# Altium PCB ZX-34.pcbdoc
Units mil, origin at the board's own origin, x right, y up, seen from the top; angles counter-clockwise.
Board outline 1066.93 x 1196.85 mil, 2 copper layers (Top Layer, Bottom Layer); 1 components, 0 nets, 21 pads, 0 vias.
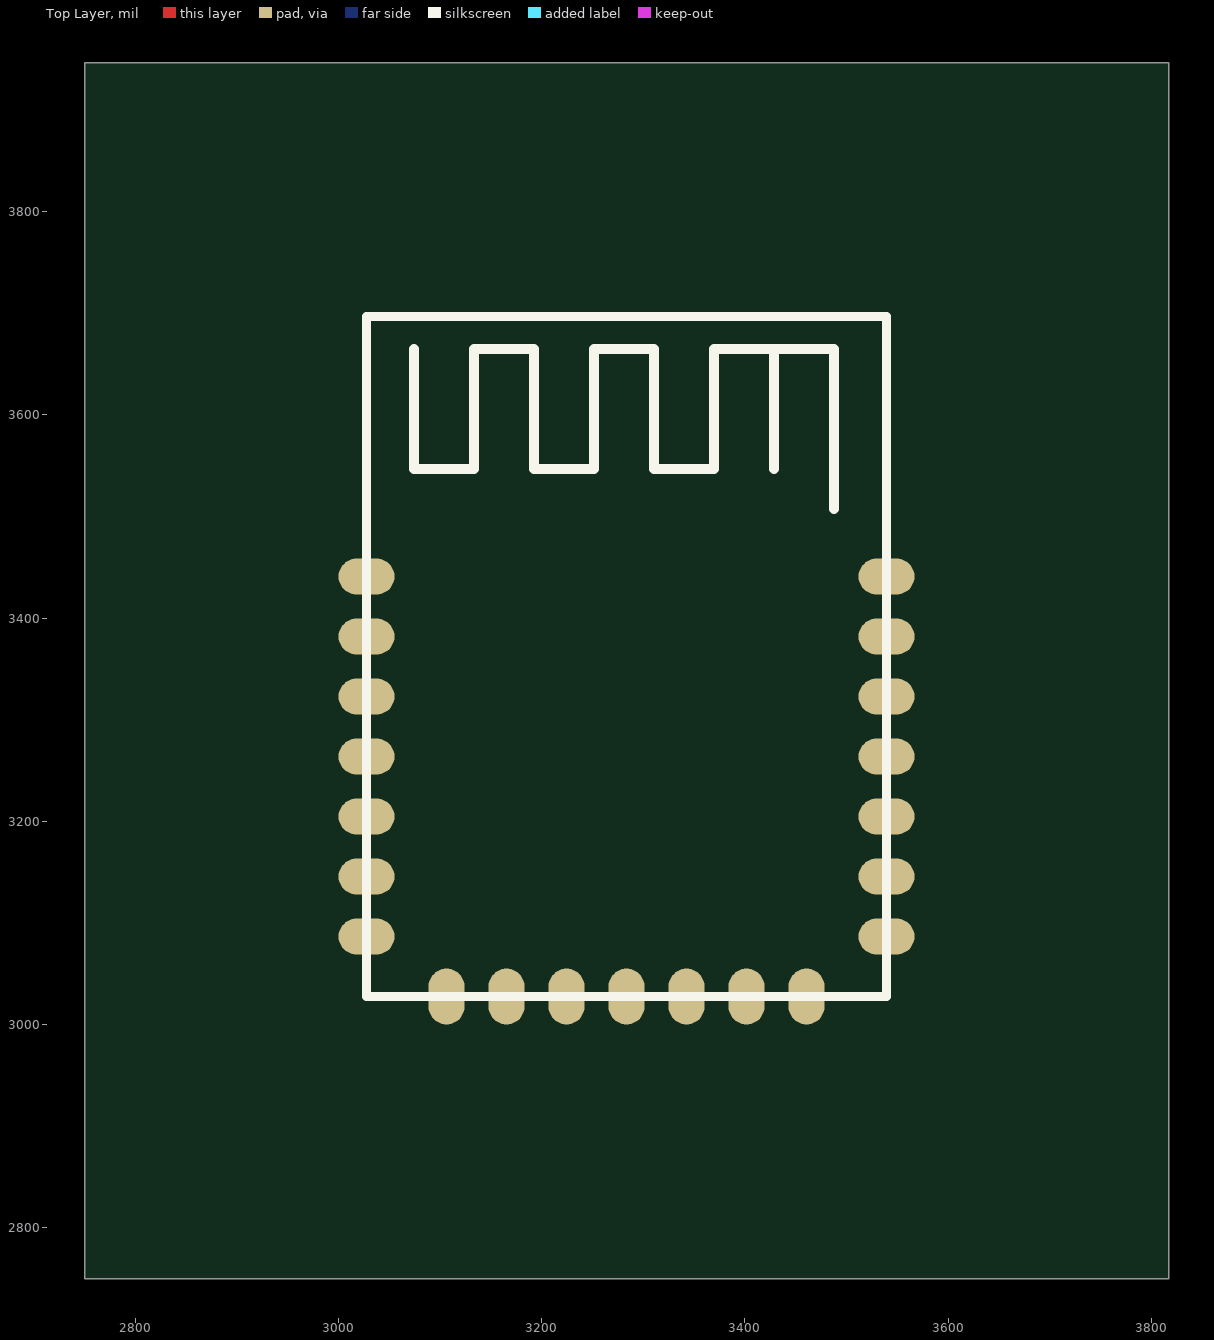
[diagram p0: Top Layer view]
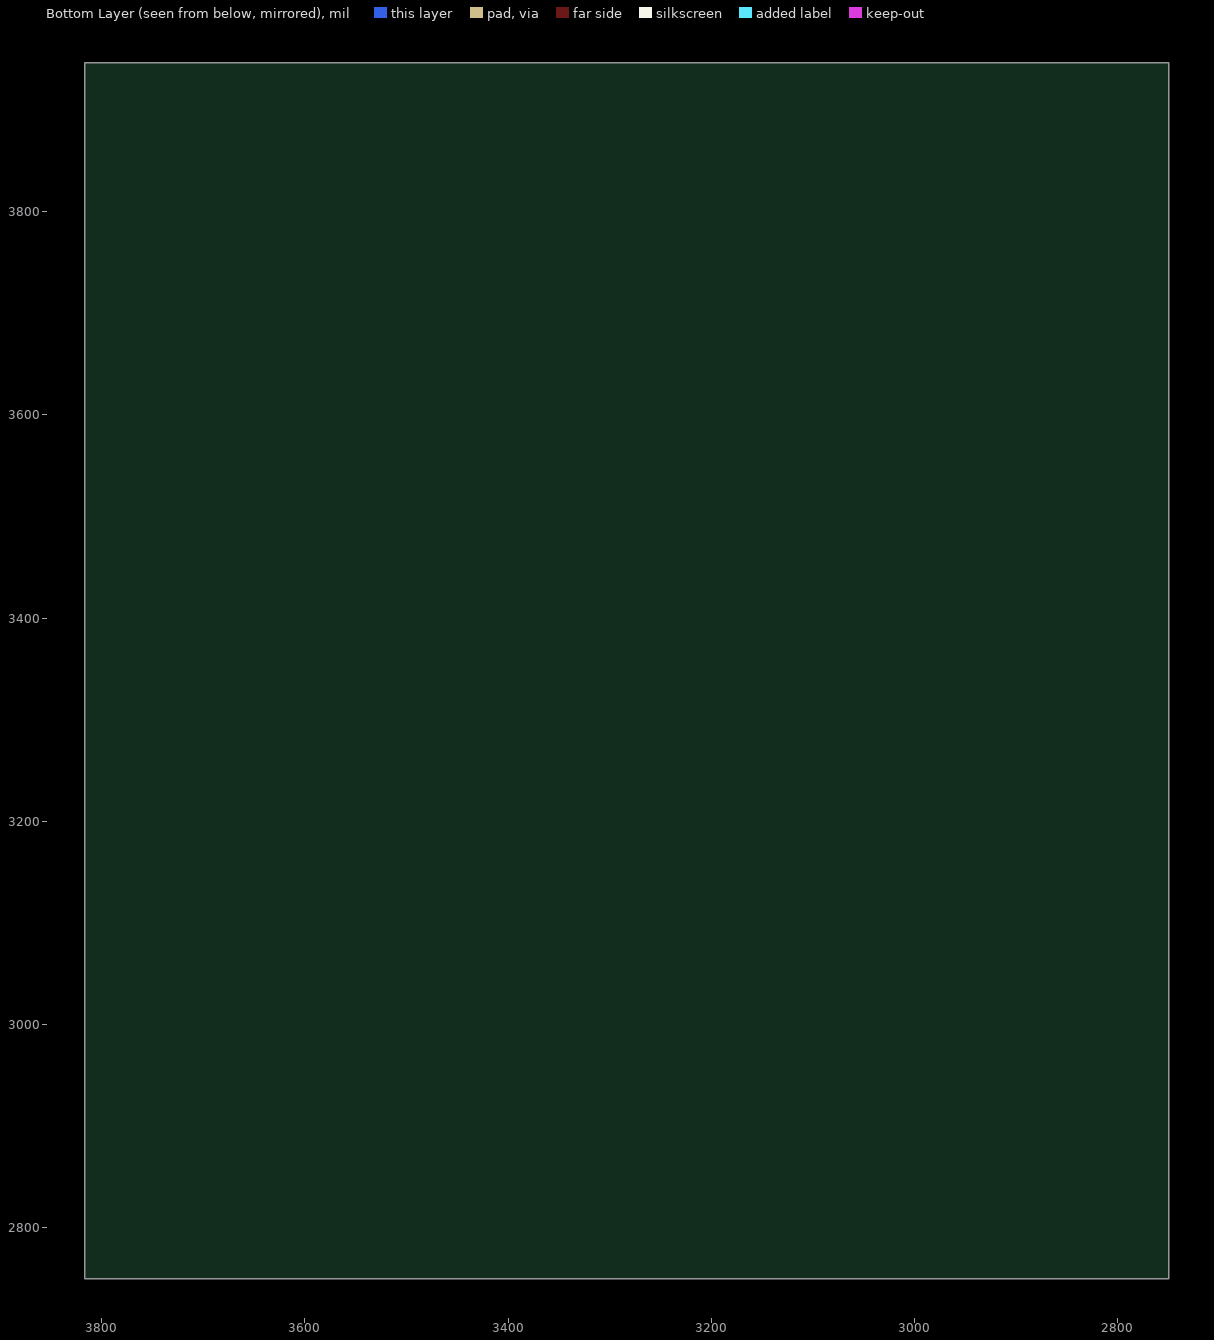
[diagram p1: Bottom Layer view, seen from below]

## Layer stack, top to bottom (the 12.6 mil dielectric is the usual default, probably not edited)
Top Solder Mask Layer: solder mask 0.4, Solder Resist, Dk 3.5
Top Layer: signal copper 1.4
Dielectric1: dielectric 12.6, FR-4, Dk 4.8
Bottom Layer: signal copper 1.4
Bottom Solder Mask Layer: solder mask 0.4, Solder Resist, Dk 3.5

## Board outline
3816.93,2750 2750,2750 2750,3946.85 3816.93,3946.85

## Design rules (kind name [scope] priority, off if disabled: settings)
BoardOutlineClearance safeClearance_1 [All] p1: gap=10 ignorepadtopadclearanceinfootprint=FALSE except(0: Arc-SplitContinuation Track-SplitContinuation SMDPad-SplitContinuation THPad-SplitContinuation Via-SplitContinuation Fill-SplitContinuation Poly-SplitContinuation Region-SplitContinuation Text-SplitContinuation; 6: Track-CutoutEdge SMDPad-CutoutEdge THPad-CutoutEdge Via-CutoutEdge Fill-CutoutEdge Region-CutoutEdge; 11.8: Track-OutlineEdge SMDPad-OutlineEdge THPad-OutlineEdge Via-OutlineEdge Fill-OutlineEdge Poly-OutlineEdge Region-OutlineEdge Text-OutlineEdge)
Clearance safeClearance [All] p1: gap=6 ignorepadtopadclearanceinfootprint=FALSE except(6.9: Track-Hole SMDPad-Hole THPad-Hole Via-Hole Fill-Hole Poly-Hole Region-Hole Text-Hole; 7: Arc-Arc Arc-Track Arc-SMDPad Arc-THPad Arc-Via Arc-Fill Arc-Poly Arc-Region Arc-Text Arc-Hole)
DiffPairsRouting differentialPair [All] p1: maxlimit=6 minlimit=6 mostfreqgap=6 toplayer_minwidth=5 toplayer_maxwidth=100 toplayer_prefwidth=10 bottomlayer_minwidth=5 bottomlayer_maxwidth=100 bottomlayer_prefwidth=10 maxuncoupledlength=10
PasteMaskExpansion pasteMaskExpansion [All] p1: expansion=0
PlaneConnect innerPlane [All] p1: planeconnectstyle=Relief reliefexpansion=20 reliefentries=4 reliefconductorwidth=10 reliefairgap=10
PolygonConnect copperRegion [All] p1: connectstyle=Relief reliefconductorwidth=10 reliefentries=4 polygonreliefangle="90 Angle" airgapwidth=10
RoutingVias viaSize [All] p1: holewidth=12.01 width=24.02 viastyle="Through Hole" minholewidth=11.81 minwidth=19.68 maxholewidth=236.22 maxwidth=393.7
SolderMaskExpansion solderMaskExpansion [All] p1: expansion=2 istentingtop=FALSE useseparateexpansions=TRUE expansionbottom=2 istentingbottom=FALSE
Width trackWidth [All] p1: maxlimit=100 minlimit=5 preferedwidth=10
27 further rules are at their usual default settings.

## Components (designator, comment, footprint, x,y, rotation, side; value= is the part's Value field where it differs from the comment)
? "W34" ZX-D34 3027.56,3027.56 r0 top

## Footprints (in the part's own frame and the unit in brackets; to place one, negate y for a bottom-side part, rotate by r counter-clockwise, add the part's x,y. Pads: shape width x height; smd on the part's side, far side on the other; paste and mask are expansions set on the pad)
ZX-D34 [mm]
  oval 1.4x0.9 smd: 1(0,10.5) 2(0,9) 3(0,7.5) 4(0,6) 5(0,4.5) 6(0,3) 7(0,1.5) 15(13,1.5) 16(13,3) 17(13,4.5) 18(13,6) 19(13,7.5) 20(13,9) 21(13,10.5)
  oval 0.9x1.4 smd: 8(2,0) 9(3.5,0) 10(5,0) 11(6.5,0) 12(8,0) 13(9.5,0) 14(11,0)
  silkscreen extent 0,0 13,17

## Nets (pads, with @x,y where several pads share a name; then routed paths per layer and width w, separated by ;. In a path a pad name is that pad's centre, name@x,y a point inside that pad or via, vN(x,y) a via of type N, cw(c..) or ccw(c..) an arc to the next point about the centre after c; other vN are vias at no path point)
pads on no net: ?.1 ?.2 ?.3 ?.4 ?.5 ?.6 ?.7 ?.8 ?.9 ?.10 ?.11 ?.12 ?.13 ?.14 ?.15 ?.16 ?.17 ?.18 ?.19 ?.20 ?.21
